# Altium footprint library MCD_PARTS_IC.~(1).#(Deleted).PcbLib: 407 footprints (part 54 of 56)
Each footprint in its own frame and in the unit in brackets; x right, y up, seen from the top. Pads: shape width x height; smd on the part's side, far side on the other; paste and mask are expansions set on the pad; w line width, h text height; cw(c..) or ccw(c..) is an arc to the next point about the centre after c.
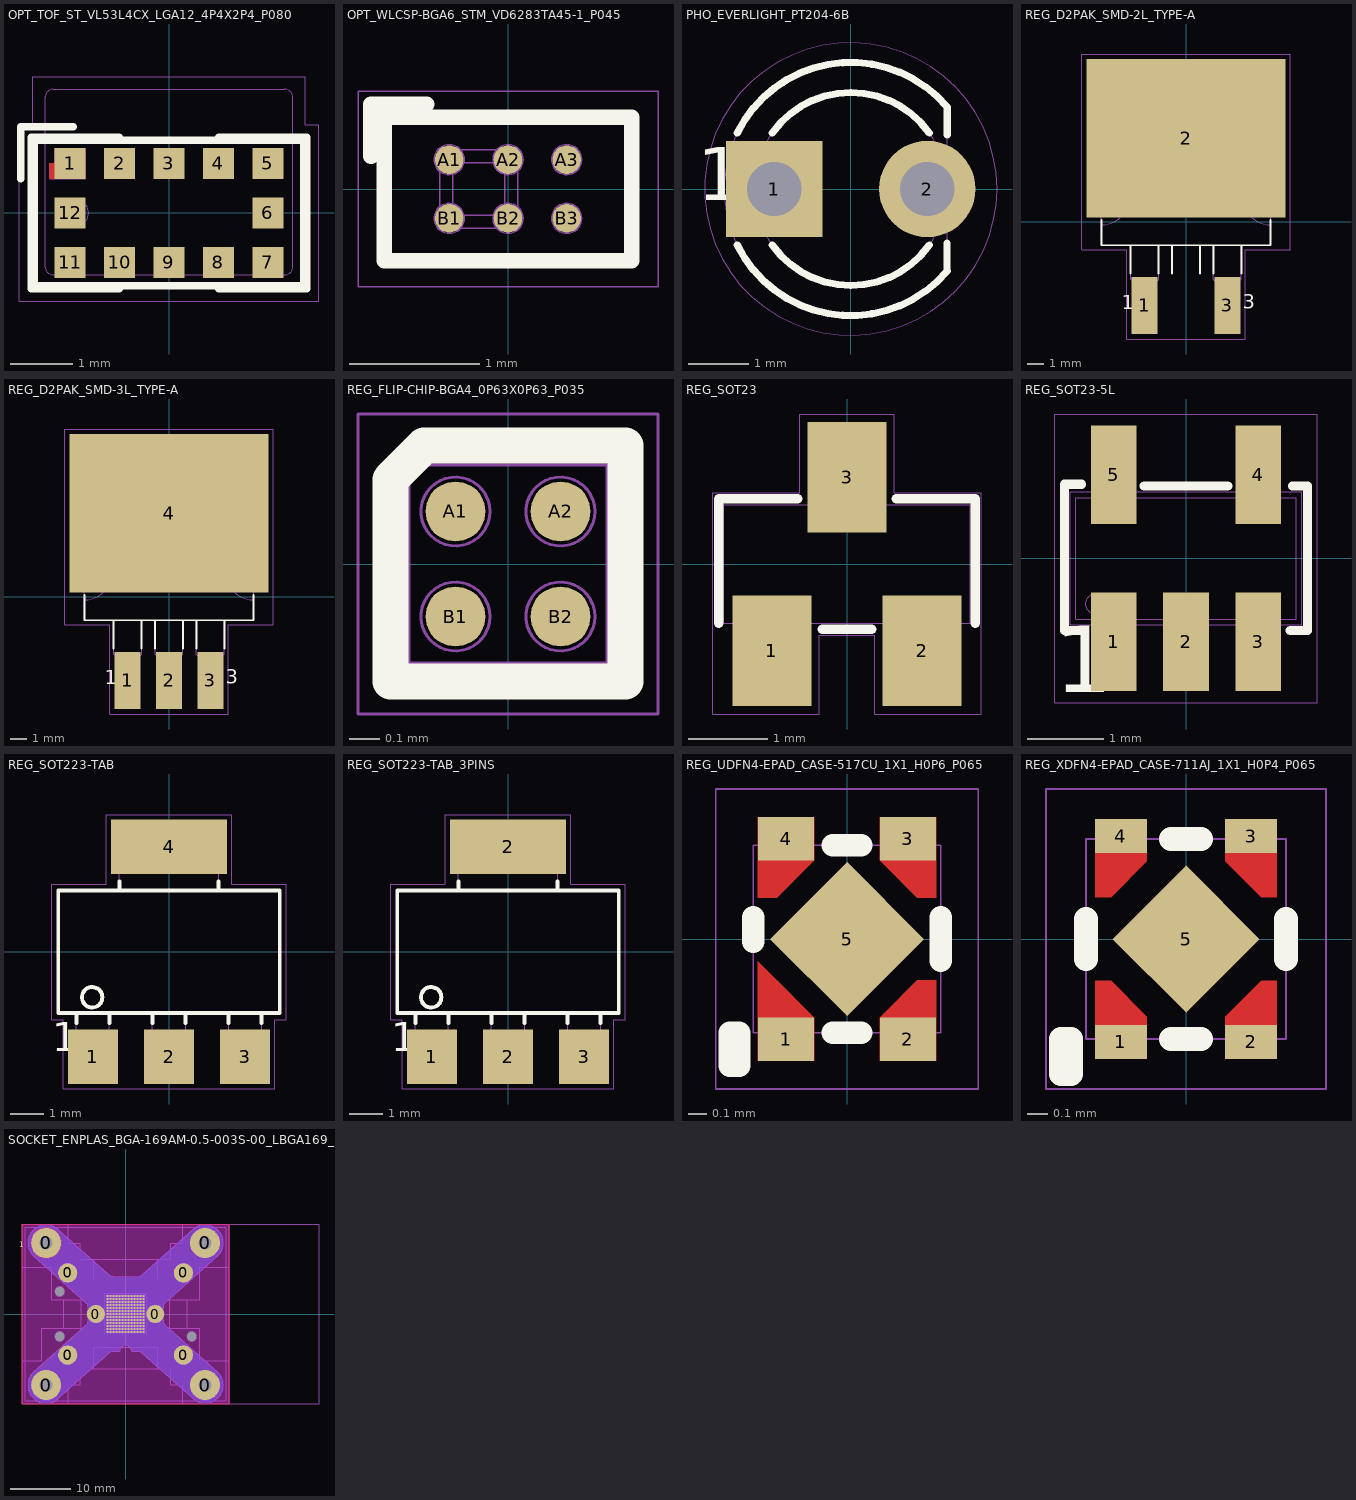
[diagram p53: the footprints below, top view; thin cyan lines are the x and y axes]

## OPT_TOF_ST_VL53L4CX_LGA12_4P4X2P4_P080 [mm]
height 1.1
pads (12):
  rect 0.5x0.5 smd mask+0.05: 1(-1.6,0.8) 2(-0.8,0.8) 3(0,0.8) 4(0.8,0.8) 5(1.6,0.8) 6(1.6,0) 7(1.6,-0.8) 8(0.8,-0.8) 9(0,-0.8) 10(-0.8,-0.8) 11(-1.6,-0.8) 12(-1.6,0)
Top Layer:
  region: -1.35,0.55 -1.93,0.55 -1.93,0.8 -1.85,0.8 -1.85,1.05 -1.35,1.05
Top Overlay:
  lines w0.12: -2.395,0.55 -2.395,1.395 -1.55,1.395 ; -0.8,-1.175 -0.8,-1.225 -2.225,-1.225 -2.225,1.225 -0.8,1.225 -0.8,1.175 ; 0.8,-1.175 0.8,-1.225 2.225,-1.225 2.225,1.225 0.8,1.225 0.8,1.175 ; -2.175,-1.175 2.175,-1.175 2.175,1.175 -2.175,1.175 -2.175,-1.175
M14-Top Assembly:
  circle w0.01: c1.5,0 r0.1
  circle w0.01: c-1.5,0 r0.2
  lines w0.01: -0.8,-1.175 -0.8,-1.225 -2.225,-1.225 -2.225,1.225 -0.8,1.225 -0.8,1.175 ; 0.8,-1.175 0.8,-1.225 2.225,-1.225 2.225,1.225 0.8,1.225 0.8,1.175 ; -2.175,-1.175 -2.175,1.175 2.175,1.175 2.175,-1.175 -2.175,-1.175 ; -2,-0.875 ccw(c-1.875,-0.875) -1.875,-1 1.875,-1 ccw(c1.875,-0.875) 2,-0.875 2,1.225 2,1.875 ccw(c1.875,1.875) 1.875,2 -1.875,2 ccw(c-1.875,1.875) -2,1.875 -2,-0.875 ; -1.93,0.55 -1.35,0.55 -1.35,1.05 -1.85,1.05 -1.85,0.8 -1.93,0.8 -1.93,0.55
  text "1" at -1.655,0.64 h0.5
  text "'.Designator'" at -2,-0.5 h0.75
  text "PROTECTIVE LINE" at -1.25,1.75 h0.3
  text "RESTRICTED ZONE H = 1mm" at -1.825,1.45 h0.3
M16-Top Courtyard:
  lines w0.01: -2.425,-1.425 -2.425,1.425 -2.2,1.425 -2.2,2.2 2.2,2.2 2.2,1.425 2.425,1.425 2.425,-1.425 -2.425,-1.425
  text "RESTRICTED ZONE H = 1mm" at -1.825,1.45 h0.3
  text "PROTECTIVE LINE" at -1.25,1.75 h0.3
3D body: height 1.08, standoff 1.04, extent -2,-1 2,2
3D body: height 1.1, standoff 0, extent -2.225,-1.225 2.225,1.225
3D body "vl53l0x.STEP": height 1.04, standoff 0, extent -2.2,-1.2 2.2,1.2

## OPT_WLCSP-BGA6_STM_VD6283TA45-1_P045 [mm] "MCD-02258"
height 0.615
pads (6):
  round 0.22 smd paste+0.025 mask+0.05: A1(-0.45,0.225) A2(0,0.225) A3(0.45,0.225) B1(-0.45,-0.225) B2(0,-0.225) B3(0.45,-0.225)
Top Overlay:
  lines w0.12: -1.05,0.25 -1.05,0.65 -0.625,0.65 ; -0.95,-0.55 -0.95,0.55 0.95,0.55 0.95,-0.55 -0.95,-0.55
M14-Top Assembly:
  circle w0.01: c-0.45,-0.225 r0.115
  circle w0.01: c0,-0.225 r0.115
  circle w0.01: c0.45,-0.225 r0.115
  circle w0.01: c0.45,0.225 r0.115
  circle w0.01: c0,0.225 r0.115
  circle w0.01: c-0.45,0.225 r0.115
  lines w0.01: -0.95,-0.55 0.95,-0.55 0.95,0.55 -0.95,0.55 -0.95,-0.55 ; -0.525,-0.3 -0.525,0.3 0.075,0.3 0.075,-0.3 -0.525,-0.3 ; -0.425,-0.2 -0.425,0.2 -0.025,0.2 -0.025,-0.2 -0.425,-0.2
  text "A1" at -0.9,0.15 h0.3
  text "'.Designator'" at -2,-0.375 h0.75
  text "B1" at -0.9,-0.325 h0.3
M16-Top Courtyard:
  lines w0.01: -1.15,-0.75 -1.15,0.75 1.15,0.75 1.15,-0.75 -1.15,-0.75
3D body: height 0.35, standoff 0.29, extent -0.313,-0.037 -0.238,0.038
3D body: height 0.35, standoff 0.29, extent -0.563,0.088 -0.488,0.163
3D body: height 0.35, standoff 0.29, extent -0.687,-0.287 -0.613,-0.212
3D body: height 0.35, standoff 0.29, extent -0.813,-0.162 -0.738,-0.088
3D body: height 0.35, standoff 0.29, extent -0.813,-0.037 -0.738,0.038
3D body: height 0.35, standoff 0.29, extent -0.687,-0.162 -0.613,-0.088
3D body: height 0.35, standoff 0.29, extent -0.563,-0.287 -0.488,-0.212
3D body: height 0.35, standoff 0.29, extent -0.313,0.088 -0.238,0.163
3D body: height 0.35, standoff 0.29, extent -0.437,0.213 -0.363,0.288
3D body: height 0.35, standoff 0.29, extent -0.437,0.088 -0.363,0.162
3D body: height 0.35, standoff 0.29, extent -0.563,0.213 -0.488,0.288
3D body: height 0.35, standoff 0.29, extent -0.313,-0.162 -0.238,-0.088
3D body: height 0.35, standoff 0.29, extent -0.437,-0.037 -0.363,0.038
3D body: height 0.35, standoff 0.29, extent -0.687,0.213 -0.613,0.288
3D body: height 0.35, standoff 0.29, extent -0.313,-0.287 -0.238,-0.212
3D body: height 0.35, standoff 0.29, extent -0.437,-0.162 -0.363,-0.088
3D body: height 0.35, standoff 0.29, extent -0.563,-0.037 -0.488,0.038
3D body: height 0.35, standoff 0.29, extent -0.687,0.088 -0.613,0.163
3D body: height 0.35, standoff 0.29, extent -0.813,0.213 -0.738,0.288
3D body: height 0.62, standoff 0.29, extent -0.95,-0.55 0.95,0.55
3D body: height 0.29, standoff 0.15, extent -0.95,-0.55 0.95,0.55
3D body: height 0.19, standoff -0.05, extent -0.558,-0.338 -0.335,-0.112
3D body: height 0.19, standoff -0.05, extent -0.108,-0.338 0.115,-0.112
3D body: height 0.19, standoff -0.05, extent 0.342,-0.338 0.565,-0.112
3D body: height 0.19, standoff -0.05, extent 0.342,0.112 0.565,0.338
3D body: height 0.19, standoff -0.05, extent -0.108,0.112 0.115,0.338
3D body: height 0.19, standoff -0.05, extent -0.558,0.112 -0.335,0.338

## PHO_EVERLIGHT_PT204-6B [mm] "MCD-01691"
height 7
pads (2):
  rect 1.6x1.6 hole 0.9 mask+0.05: 1(-1.27,0)
  round 1.6 hole 0.9 mask+0.05: 2(1.27,0)
Top Overlay:
  lines w0.12: -1.883,-0.929 ccw(c0,0) 1.599,-1.361 ; -1.883,0.929 cw(c0,0) 1.599,1.362 ; -1.304,-0.928 ccw(c0,0) 1.304,-0.928 ; -1.304,0.928 cw(c0,0) 1.304,0.928 ; 1.598,-1.361 1.598,-0.9 ; 1.6,0.9 1.6,1.362
  text "1" at -2.55,-0.475 h1.5
M14-Top Assembly:
  circle w0.01: c0,0 r1.6
  lines w0.01: 1.599,1.362 ccw(c0,0) 1.6,-1.36 1.6,1.362
  text "C" at 1.1,-0.25 h0.75
  text "E" at -1.525,-0.225 h0.75
  text "'.Designator'" at -2,0.25 h0.75
M16-Top Courtyard:
  circle w0.01: c0,0 r2.425
3D body: height 0.55, standoff -0.05, extent 0.97,-0.298 1.57,0.298
3D body: height 1.5, standoff 0.25, extent 0.973,-0.299 1.57,0.3
3D body: height 0, standoff -23.9, extent 1.02,-0.2 1.52,0.2
3D body: height 0.15, standoff 0, extent 1.02,-0.2 1.52,0.2
3D body: height 0.15, standoff 0, extent -1.52,-0.2 -1.02,0.2
3D body: height 0, standoff -24.9, extent -1.52,-0.2 -1.02,0.2
3D body: height 1.5, standoff 0.25, extent -1.567,-0.299 -0.97,0.3
3D body: height 0.55, standoff -0.05, extent -1.57,-0.298 -0.97,0.298
3D body: height 2.7, standoff 1.5, extent -2.1,-2.1 1.6,2.1
3D body: height 5.4, standoff 2.7, extent -1.6,-1.597 1.6,1.597
3D body: height 7, standoff 3.8, extent -1.588,-1.597 1.6,1.597

## REG_D2PAK_SMD-2L_TYPE-A [mm] "MCD-03390"
height 4.6
pads (3):
  rect 1.6x3.5 smd paste+0 mask+0.05: 1(-2.54,-5.138) 3(2.54,-5.138)
  rect 12.2x9.75 smd mask+0.05: 2(0,5.138)
Top Overlay:
  lines w0.12: -5.2,0.112 -5.2,-1.438 5.2,-1.438 5.2,0.112 ; -3.4,-3.188 -3.4,-1.438 ; -1.7,-3.188 -1.7,-1.438 ; -0.85,-3.188 -0.85,-1.438 ; 0.85,-3.188 0.85,-1.438 ; 1.7,-3.188 1.7,-1.438 ; 3.4,-3.188 3.4,-1.438
  text "1" at -3.95,-5.688 h1.5
  text "3" at 3.5,-5.638 h1.5
M14-Top Assembly:
  lines w0.01: -5.2,-0.188 ccw(c-5.2,1.512) -5.2,3.212 ; -5.2,6.912 5.2,6.912 ; -3.39,-1.438 -3.39,-3.538 -3.19,-3.738 ; -3.19,-1.438 -1.69,-1.438 -1.69,-3.538 -1.89,-3.738 ; 1.69,-1.438 1.69,-3.538 1.89,-3.738 ; 1.89,-1.438 3.39,-1.438 3.39,-3.538 3.19,-3.738 ; 5.2,-0.188 cw(c5.2,1.512) 5.2,3.212 ; -5.2,7.912 -5.2,-1.438 5.2,-1.438 5.2,7.912 ; -5.2,7.912 5.2,7.912 ; -5.2,7.912 -5.2,9.312 5.2,9.312 5.2,7.912 ; -3.19,-3.738 -1.89,-3.738 ; -3.19,-3.738 -1.89,-3.738 ; 1.89,-3.738 3.19,-3.738 ; 1.89,-3.738 3.19,-3.738 ; -3.04,-6.538 -3.04,-3.738 -2.04,-3.738 -2.04,-6.538 -3.04,-6.538 ; 2.04,-6.538 2.04,-3.738 3.04,-3.738 3.04,-6.538 2.04,-6.538
  text "2" at -0.35,3.312 h1.5
  text "1" at -2.743,-6.272 h1.5
  text "3" at 2.257,-6.297 h1.5
  text "'.Designator'" at 0,0 h0.75
M16-Top Courtyard:
  lines w0.01: -6.4,-1.7 -6.4,0.85 -6.4,4.4 -6.4,10.3 6.4,10.3 6.4,-1.7 5.45,-1.7 3.65,-1.7 3.65,-7.2 -3.65,-7.2 -3.65,-3.75 -3.65,-1.7 -5.45,-1.7 -6.4,-1.7
3D body: height 2.7, standoff 2.4, extent -0.85,-4.038 0.85,-1.438
3D body: height 2.7, standoff 0.3, extent 2.04,-4.038 3.04,-3.738
3D body: height 2.7, standoff 0.3, extent -3.04,-4.038 -2.04,-3.738
3D body: height 0.3, standoff 0, extent 2.04,-6.538 3.04,-3.738
3D body: height 2.7, standoff 2.4, extent 1.69,-4.038 3.39,-1.438
3D body: height 0.3, standoff 0, extent -3.04,-6.538 -2.04,-3.738
3D body: height 2.7, standoff 2.4, extent -3.39,-4.038 -1.69,-1.438
3D body: height 4.6, standoff 1.4, extent -5.2,-1.438 5.2,7.912
3D body: height 1.4, standoff 0, extent -5.2,-1.438 5.2,7.912
3D body: height 1.4, standoff 0, extent -5.2,7.912 5.2,9.312

## REG_D2PAK_SMD-3L_TYPE-A [mm] "MCD-02365"
height 4.6
pads (4):
  rect 1.6x3.5 smd paste+0 mask+0.05: 1(-2.54,-5.138) 2(0,-5.138) 3(2.54,-5.138)
  rect 12.2x9.75 smd mask+0.05: 4(0,5.138)
Top Overlay:
  lines w0.12: -5.2,0.112 -5.2,-1.438 5.2,-1.438 5.2,0.112 ; -3.4,-3.188 -3.4,-1.438 ; -1.7,-3.188 -1.7,-1.438 ; -0.85,-3.188 -0.85,-1.438 ; 0.85,-3.188 0.85,-1.438 ; 1.7,-3.188 1.7,-1.438 ; 3.4,-3.188 3.4,-1.438
  text "1" at -3.95,-5.688 h1.5
  text "3" at 3.5,-5.638 h1.5
M14-Top Assembly:
  lines w0.01: -5.2,-0.188 ccw(c-5.2,1.512) -5.2,3.212 ; -5.2,6.912 5.2,6.912 ; -3.39,-1.438 -3.39,-3.538 -3.19,-3.738 ; -3.19,-1.438 -1.69,-1.438 -1.69,-3.538 -1.89,-3.738 ; -0.85,-1.438 -0.85,-3.538 -0.65,-3.738 ; -0.65,-1.438 0.85,-1.438 0.85,-3.538 0.65,-3.738 ; 1.69,-1.438 1.69,-3.538 1.89,-3.738 ; 1.89,-1.438 3.39,-1.438 3.39,-3.538 3.19,-3.738 ; 5.2,-0.188 cw(c5.2,1.512) 5.2,3.212 ; -5.2,7.912 -5.2,-1.438 5.2,-1.438 5.2,7.912 ; -5.2,7.912 5.2,7.912 ; -5.2,7.912 -5.2,9.312 5.2,9.312 5.2,7.912 ; -3.19,-3.738 -1.89,-3.738 ; -3.19,-3.738 -1.89,-3.738 ; -0.65,-3.738 0.65,-3.738 ; -0.65,-3.738 -0.65,-6.538 0.65,-6.538 0.65,-3.738 ; -0.65,-3.738 0.65,-3.738 ; 1.89,-3.738 3.19,-3.738 ; 1.89,-3.738 3.19,-3.738 ; -3.04,-6.538 -3.04,-3.738 -2.04,-3.738 -2.04,-6.538 -3.04,-6.538 ; 2.04,-6.538 2.04,-3.738 3.04,-3.738 3.04,-6.538 2.04,-6.538
  text "4" at -0.35,3.312 h1.5
  text "1" at -2.743,-6.272 h1.5
  text "3" at 2.257,-6.297 h1.5
  text "2" at -0.293,-6.297 h1.5
  text "'.Designator'" at -2,-0.5 h0.75
M16-Top Courtyard:
  lines w0.01: -6.4,-1.7 -6.4,0.85 -6.4,4.4 -6.4,10.3 6.4,10.3 6.4,-1.7 5.45,-1.7 3.65,-1.7 3.65,-7.2 -3.65,-7.2 -3.65,-3.75 -3.65,-1.7 -5.45,-1.7 -6.4,-1.7
3D body: height 2.7, standoff 0.3, extent 2.04,-4.038 3.04,-3.738
3D body: height 2.7, standoff 0.3, extent -0.65,-4.038 0.65,-3.738
3D body: height 2.7, standoff 0.3, extent -3.04,-4.038 -2.04,-3.738
3D body: height 0.3, standoff 0, extent 2.04,-6.538 3.04,-3.738
3D body: height 2.7, standoff 2.4, extent 1.69,-4.038 3.39,-1.438
3D body: height 2.7, standoff 2.4, extent -0.85,-4.038 0.85,-1.438
3D body: height 0.3, standoff 0, extent -0.65,-6.538 0.65,-3.738
3D body: height 0.3, standoff 0, extent -3.04,-6.538 -2.04,-3.738
3D body: height 2.7, standoff 2.4, extent -3.39,-4.038 -1.69,-1.438
3D body: height 4.6, standoff 1.4, extent -5.2,-1.438 5.2,7.912
3D body: height 1.4, standoff 0, extent -5.2,-1.438 5.2,7.912
3D body: height 1.4, standoff 0, extent -5.2,7.912 5.2,9.312

## REG_FLIP-CHIP-BGA4_0P63X0P63_P035 [mm] "MCD-03556"
height 0.45
pads (4):
  round 0.2 smd paste+0.019 mask+0.038: A1(-0.175,0.175) A2(0.175,0.175) B1(-0.175,-0.175) B2(0.175,-0.175)
Top Overlay:
  lines w0.12: 0.392,0.394 -0.28,0.394 -0.392,0.282 -0.392,0.28 -0.392,-0.392 0.392,-0.392 0.392,0.392
M14-Top Assembly:
  circle w0.01: c-0.175,0.175 r0.115
  circle w0.01: c-0.175,-0.175 r0.115
  circle w0.01: c0.175,0.175 r0.115
  circle w0.01: c0.175,-0.175 r0.115
  lines w0.01: -0.33,-0.33 -0.33,0.33 0.33,0.33 0.33,-0.33 -0.33,-0.33
  text "'.Designator'" at -2,-0.5 h0.75
  text "A1" at -0.314,0.079 h0.3
M16-Top Courtyard:
  lines w0.01: -0.5,-0.5 0.5,-0.5 0.5,0.5 -0.5,0.5 -0.5,-0.5
3D body: height 0.23, standoff -0.01, extent 0.055,0.055 0.295,0.295
3D body: height 0.45, standoff 0.21, extent -0.33,-0.33 0.33,0.33
3D body: height 0.46, standoff 0.45, extent -0.275,0.075 -0.075,0.275
3D body: height 0.23, standoff -0.01, extent -0.295,0.055 -0.055,0.295
3D body: height 0.23, standoff -0.01, extent -0.295,-0.295 -0.055,-0.055
3D body: height 0.23, standoff -0.01, extent 0.055,-0.295 0.295,-0.055

## REG_SOT23 [mm]
height 1.1
pads (3):
  rect 1x1.4 smd mask+0.05: 1(-0.95,-1.1) 2(0.95,-1.1) 3(0,1.1)
Top Overlay:
  lines w0.12: -1.625,-0.75 -1.625,0.825 -0.624,0.825 ; -0.312,-0.825 0.312,-0.825 ; 0.624,0.825 1.625,0.825 1.625,-0.75
M14-Top Assembly:
  lines w0.01: -1.56,-0.75 1.56,-0.75 1.56,0.75 -1.56,0.75 -1.56,-0.75 ; -1.275,-1.025 -1.275,-0.75 -0.675,-0.75 -0.675,-1.025 -1.275,-1.025 ; -0.25,0.75 -0.25,1.05 0.325,1.05 0.325,0.75 -0.25,0.75 ; 0.65,-1.025 0.65,-0.75 1.25,-0.75 1.25,-1.025 0.65,-1.025
  text "'.Designator'" at -2,-0.5 h0.75
M16-Top Courtyard:
  lines w0.01: -1.7,-1.9 -1.7,0.9 -0.6,0.9 -0.6,1.9 0.6,1.9 0.6,0.9 1.7,0.9 1.7,-1.9 0.35,-1.9 0.35,-0.9 -0.35,-0.9 -0.35,-1.9 -1.7,-1.9
3D body "SOT23-3_TO-236AB.STEP": height 1.09, standoff 0, extent -1.5,-1.25 1.5,1.25
3D body: height 1.1, standoff 0, extent -1.559,-0.749 1.559,0.749

## REG_SOT23-5L [mm]
height 0.9
pads (5):
  rect 0.6x1.3 smd mask+0.05: 1(-0.95,-1.1) 2(0,-1.1) 3(0.95,-1.1) 4(0.95,1.1) 5(-0.95,1.1)
Top Overlay:
  lines w0.12: -1.375,0.975 -1.6,0.975 -1.6,-0.95 -1.372,-0.95 ; -0.55,0.95 0.55,0.95 ; 1.372,-0.95 1.6,-0.95 1.6,0.95 1.4,0.95
  text "1" at -1.725,-2.05 h1.5
M14-Top Assembly:
  circle w0.01: c-1.2,-0.6 r0.125
  lines w0.01: -1.15,-0.875 -1.15,-1.5 -0.75,-1.5 -0.75,-0.875 ; -1.15,0.875 -1.15,1.5 -0.75,1.5 -0.75,0.875 ; -0.2,-0.875 -0.2,-1.5 0.2,-1.5 0.2,-0.875 ; 0.75,-0.875 0.75,-1.5 1.15,-1.5 1.15,-0.875 ; 0.75,0.875 0.75,1.5 1.15,1.5 1.15,0.875 ; -1.525,-0.875 -1.525,0.875 1.525,0.875 1.525,-0.875 -1.525,-0.875 ; -1.45,-0.8 1.45,-0.8 1.45,0.8 -1.45,0.8 -1.45,-0.8
  text "'.Designator'" at -2,-0.5 h0.75
M16-Top Courtyard:
  lines w0.01: -1.725,-1.9 -1.725,1.9 1.725,1.9 1.725,-1.9 -1.725,-1.9
3D body "SOT23-5L.STEP": height 1.1, standoff 0, extent -1.5,-1.25 1.5,1.25
3D body: height 0.9, standoff 0, extent -1.524,-0.874 1.524,0.874

## REG_SOT223-TAB [mm]
height 1.8
pads (4):
  rect 1.5x1.65 smd mask+0.05: 1(-2.3,-3.175) 2(0,-3.175) 3(2.3,-3.175)
  rect 3.5x1.65 smd mask+0.05: 4(0,3.175)
Top Overlay:
  circle w0.12: c-2.325,-1.375 r0.309
  lines w0.12: -2.8,-2.15 -2.8,-1.85 -1.8,-1.85 -1.8,-2.15 ; -1.5,2.125 -1.5,1.85 1.5,1.85 1.5,2.125 ; -0.5,-2.15 -0.5,-1.85 0.5,-1.85 0.5,-2.15 ; 1.8,-2.15 1.8,-1.85 2.8,-1.85 2.8,-2.15 ; -3.35,-1.85 -3.35,1.85 3.35,1.85 3.35,-1.85 -3.35,-1.85
  text "1" at -3.525,-3.3 h1.5
M14-Top Assembly:
  circle w0.01: c-2.325,-1.375 r0.285
  lines w0.01: -3.35,-1.85 -3.35,1.85 3.35,1.85 3.35,-1.85 -3.35,-1.85 ; -2.8,-3.65 -1.8,-3.65 -1.8,-1.85 -2.8,-1.85 -2.8,-3.65 ; -1.5,1.85 1.5,1.85 1.5,3.65 -1.5,3.65 -1.5,1.85 ; -0.5,-3.65 0.5,-3.65 0.5,-1.85 -0.5,-1.85 -0.5,-3.65 ; 1.8,-3.65 2.8,-3.65 2.8,-1.85 1.8,-1.85 1.8,-3.65
  text "'.Designator'" at -2,-0.5 h0.75
  text "3" at 1.95,-3.4 h1.5
  text "2" at -0.35,-3.375 h1.5
  text "1" at -2.5,-3.35 h1.5
  text "4" at -0.325,2.375 h1.5
M16-Top Courtyard:
  lines w0.01: -3.55,-2.05 -3.55,2.05 -1.9,2.05 -1.9,4.15 1.9,4.15 1.9,2.05 3.55,2.05 3.55,-2.05 3.2,-2.05 3.2,-4.15 -3.2,-4.15 -3.2,-2.05 -3.55,-2.05
3D body "SOT223.STEP": height 1.68, standoff 0, extent -3.25,-3.48 3.25,3.48
3D body: height 1.8, standoff 0, extent -3.349,-1.849 3.349,1.849

## REG_SOT223-TAB_3PINS [mm] "MCD-04293"
height 1.8
pads (4):
  rect 1.5x1.65 smd mask+0.05: 1(-2.3,-3.175) 2(0,-3.175) 3(2.3,-3.175)
  rect 3.5x1.65 smd mask+0.05: 2(0,3.175)
Top Overlay:
  circle w0.12: c-2.325,-1.375 r0.309
  lines w0.12: -2.8,-2.15 -2.8,-1.85 -1.8,-1.85 -1.8,-2.15 ; -1.5,2.125 -1.5,1.85 1.5,1.85 1.5,2.125 ; -0.5,-2.15 -0.5,-1.85 0.5,-1.85 0.5,-2.15 ; 1.8,-2.15 1.8,-1.85 2.8,-1.85 2.8,-2.15 ; -3.35,-1.85 -3.35,1.85 3.35,1.85 3.35,-1.85 -3.35,-1.85
  text "1" at -3.525,-3.3 h1.5
M14-Top Assembly:
  circle w0.01: c-2.325,-1.375 r0.285
  lines w0.01: -3.35,-1.85 -3.35,1.85 3.35,1.85 3.35,-1.85 -3.35,-1.85 ; -2.8,-3.65 -1.8,-3.65 -1.8,-1.85 -2.8,-1.85 -2.8,-3.65 ; -1.5,1.85 1.5,1.85 1.5,3.65 -1.5,3.65 -1.5,1.85 ; -0.5,-3.65 0.5,-3.65 0.5,-1.85 -0.5,-1.85 -0.5,-3.65 ; 1.8,-3.65 2.8,-3.65 2.8,-1.85 1.8,-1.85 1.8,-3.65
  text "'.Designator'" at 0,0 h0.75
  text "3" at 1.95,-3.4 h1.5
  text "2" at -0.35,-3.375 h1.5
  text "1" at -2.5,-3.35 h1.5
  text "2" at -0.325,2.375 h1.5
M16-Top Courtyard:
  lines w0.01: -3.55,-2.05 -3.55,2.05 -1.9,2.05 -1.9,4.15 1.9,4.15 1.9,2.05 3.55,2.05 3.55,-2.05 3.2,-2.05 3.2,-4.15 -3.2,-4.15 -3.2,-2.05 -3.55,-2.05
3D body "SOT223.STEP": height 1.68, standoff 0, extent -3.25,-3.48 3.25,3.48
3D body: height 1.8, standoff 0, extent -3.349,-1.849 3.349,1.849

## REG_UDFN4-EPAD_CASE-517CU_1X1_H0P6_P065 [mm] "MCD-01614"
height 0.6
pads (5):
  rect 0.3x0.23 smd paste-10 mask-10: 1(-0.325,-0.535) 2(0.325,-0.535) 3(0.325,0.535) 4(-0.325,0.535)
  rect 0.58x0.58 smd rot 45 paste+0 mask+0.017: 5(0,0)
Top Layer:
  region: -0.475,0.65 -0.175,0.65 -0.175,0.42 -0.375,0.22 -0.475,0.22
  region: 0.475,0.65 0.175,0.65 0.175,0.42 0.375,0.22 0.475,0.22
  region: -0.475,-0.65 -0.175,-0.65 -0.175,-0.42 -0.475,-0.12
  region: 0.475,-0.65 0.175,-0.65 0.175,-0.42 0.375,-0.22 0.475,-0.22
  lines w0.001: 0.035,-0.33 0.035,-0.33
Top Overlay:
  lines w0.12: -0.5,-0.015 -0.5,0.115 ; -0.075,-0.5 0.075,-0.5 ; -0.075,0.5 0.075,0.5 ; 0.5,-0.115 0.5,0.115 ; -0.625,-0.675 -0.625,-0.5 -0.575,-0.5 -0.575,-0.675 -0.625,-0.675
M14-Top Assembly:
  lines w0.01: -0.45,-0.5 -0.45,-0.225 -0.375,-0.225 -0.2,-0.4 -0.2,-0.5 ; -0.45,0.5 -0.45,0.225 -0.375,0.225 -0.2,0.4 -0.2,0.5 ; 0.2,-0.5 0.2,-0.4 0.375,-0.225 0.45,-0.225 0.45,-0.5 ; 0.2,0.5 0.2,0.4 0.375,0.225 0.45,0.225 0.45,0.5 ; -0.5,-0.5 0.5,-0.5 0.5,0.5 -0.5,0.5 -0.5,-0.5 ; -0.325,0 0,-0.325 0.325,0 0,0.325 -0.325,0
  text "5" at -0.05,-0.075 h0.25
  text "4" at -0.4,0.325 h0.25
  text "3" at 0.3,0.325 h0.25
  text "2" at 0.3,-0.475 h0.25
  text "1" at -0.4,-0.475 h0.25
  text "'.Designator'" at -2,-0.5 h0.75
M16-Top Courtyard:
  lines w0.01: -0.7,-0.8 -0.7,0.8 0.7,0.8 0.7,-0.8 -0.7,-0.8
3D body: height 0.6, standoff 0, extent -0.5,-0.5 0.5,0.5
3D body: height 0.61, standoff 0.6, extent -0.444,-0.445 -0.205,-0.205

## REG_XDFN4-EPAD_CASE-711AJ_1X1_H0P4_P065 [mm] "MCD-01613"
height 0.43
pads (5):
  rect 0.26x0.17 smd paste-10 mask-10: 1(-0.325,-0.515) 2(0.325,-0.515) 3(0.325,0.515) 4(-0.325,0.515)
  rect 0.52x0.52 smd rot 45 paste+0 mask+0.038: 5(0,0)
Top Layer:
  region: -0.455,0.6 -0.195,0.6 -0.195,0.39 -0.375,0.21 -0.455,0.21
  region: 0.455,0.6 0.195,0.6 0.195,0.39 0.375,0.21 0.455,0.21
  region: -0.455,-0.6 -0.195,-0.6 -0.195,-0.39 -0.375,-0.21 -0.455,-0.21
  region: 0.455,-0.6 0.195,-0.6 0.195,-0.39 0.375,-0.21 0.455,-0.21
Top Overlay:
  lines w0.12: -0.5,-0.1 -0.5,0.1 ; -0.075,-0.5 0.075,-0.5 ; -0.075,0.5 0.075,0.5 ; 0.5,-0.1 0.5,0.1 ; -0.625,-0.675 -0.575,-0.675 -0.575,-0.5 -0.625,-0.5 -0.625,-0.675
M14-Top Assembly:
  lines w0.01: -0.45,-0.5 -0.45,-0.225 -0.375,-0.225 -0.2,-0.4 -0.2,-0.5 ; -0.45,0.5 -0.45,0.225 -0.375,0.225 -0.2,0.4 -0.2,0.5 ; 0.2,-0.5 0.2,-0.4 0.375,-0.225 0.45,-0.225 0.45,-0.5 ; 0.2,0.5 0.2,0.4 0.375,0.225 0.45,0.225 0.45,0.5 ; -0.5,-0.5 -0.5,0.5 0.5,0.5 0.5,-0.5 -0.5,-0.5 ; -0.325,0 0,0.325 0.325,0 0,-0.325 -0.325,0
  text "'.Designator'" at -2,-0.5 h0.75
  text "1" at -0.4,-0.475 h0.25
  text "2" at 0.3,-0.475 h0.25
  text "3" at 0.3,0.325 h0.25
  text "4" at -0.4,0.325 h0.25
  text "5" at -0.05,-0.075 h0.25
M16-Top Courtyard:
  lines w0.01: -0.7,-0.75 0.7,-0.75 0.7,0.75 -0.7,0.75 -0.7,-0.75
3D body "XDFN4-711AJ.STEP": height 0.36, standoff -0.03, extent -0.5,-0.502 0.5,0.502
3D body: height 0.44, standoff 0.43, extent -0.444,-0.445 -0.205,-0.205
3D body: height 0.37, standoff 0.36, extent -0.469,-0.47 -0.23,-0.23
3D body: height 0.43, standoff 0, extent -0.5,-0.5 0.5,0.5

## SOCKET_ENPLAS_BGA-169AM-0.5-003S-00_LBGA169_P050_3D-CLOSE [mm] "MCD-02114"
height 41
pads (182):
  round 5 hole 2.15 mask+0.05: 0(-13.25,-11.85) 0(-13.25,11.85) 0(13.25,-11.85) 0(13.25,11.85)
  round 0 hole 1.6 unplated mask+0.05: 0(-11,-3.75) 0(-11,3.75) 0(11,-3.75)
  round 3.2 smd paste-2 mask+0.05: 0(-9.65,-6.85) 0(-9.65,6.85) 0(9.65,-6.85) 0(9.65,6.85)
  round 3 smd paste-2 mask+0.05: 0(-4.945,0) 0(4.945,0)
  rrect30% 0.35x0.35 smd paste-0.2 mask+0.05: A1(-3,3) A2(-2.5,3) A3(-2,3) A4(-1.5,3) A5(-1,3) A6(-0.5,3) A7(0,3) A8(0.5,3) A9(1,3) A10(1.5,3) A11(2,3) A12(2.5,3) A13(3,3) B1(-3,2.5) B2(-2.5,2.5) B3(-2,2.5) B4(-1.5,2.5) B5(-1,2.5) B6(-0.5,2.5) B7(0,2.5) B8(0.5,2.5) B9(1,2.5) B10(1.5,2.5) B11(2,2.5) B12(2.5,2.5) B13(3,2.5) C1(-3,2) C2(-2.5,2) C3(-2,2) C4(-1.5,2) C5(-1,2) C6(-0.5,2) C7(0,2) C8(0.5,2) C9(1,2) C10(1.5,2) C11(2,2) C12(2.5,2) C13(3,2) D1(-3,1.5) D2(-2.5,1.5) D3(-2,1.5) D4(-1.5,1.5) D5(-1,1.5) D6(-0.5,1.5) D7(0,1.5) D8(0.5,1.5) D9(1,1.5) D10(1.5,1.5) D11(2,1.5) D12(2.5,1.5) D13(3,1.5) E1(-3,1) E2(-2.5,1) E3(-2,1) E4(-1.5,1) E5(-1,1) E6(-0.5,1) E7(0,1) E8(0.5,1) E9(1,1) E10(1.5,1) E11(2,1) E12(2.5,1) E13(3,1) F1(-3,0.5) F2(-2.5,0.5) F3(-2,0.5) F4(-1.5,0.5) F5(-1,0.5) F6(-0.5,0.5) F7(0,0.5) F8(0.5,0.5) F9(1,0.5) F10(1.5,0.5) F11(2,0.5) F12(2.5,0.5) F13(3,0.5) G1(-3,0) G2(-2.5,0) G3(-2,0) G4(-1.5,0) G5(-1,0) G6(-0.5,0) G7(0,0) G8(0.5,0) G9(1,0) G10(1.5,0) G11(2,0) G12(2.5,0) G13(3,0) H1(-3,-0.5) H2(-2.5,-0.5) H3(-2,-0.5) H4(-1.5,-0.5) H5(-1,-0.5) H6(-0.5,-0.5) H7(0,-0.5) H8(0.5,-0.5) H9(1,-0.5) H10(1.5,-0.5) H11(2,-0.5) H12(2.5,-0.5) H13(3,-0.5) J1(-3,-1) J2(-2.5,-1) J3(-2,-1) J4(-1.5,-1) J5(-1,-1) J6(-0.5,-1) J7(0,-1) J8(0.5,-1) J9(1,-1) J10(1.5,-1) J11(2,-1) J12(2.5,-1) J13(3,-1) K1(-3,-1.5) K2(-2.5,-1.5) K3(-2,-1.5) K4(-1.5,-1.5) K5(-1,-1.5) K6(-0.5,-1.5) K7(0,-1.5) K8(0.5,-1.5) K9(1,-1.5) K10(1.5,-1.5) K11(2,-1.5) K12(2.5,-1.5) K13(3,-1.5) L1(-3,-2) L2(-2.5,-2) L3(-2,-2) L4(-1.5,-2) L5(-1,-2) L6(-0.5,-2) L7(0,-2) L8(0.5,-2) L9(1,-2) L10(1.5,-2) L11(2,-2) L12(2.5,-2) L13(3,-2) M1(-3,-2.5) M2(-2.5,-2.5) M3(-2,-2.5) M4(-1.5,-2.5) M5(-1,-2.5) M6(-0.5,-2.5) M7(0,-2.5) M8(0.5,-2.5) M9(1,-2.5) M10(1.5,-2.5) M11(2,-2.5) M12(2.5,-2.5) M13(3,-2.5) N1(-3,-3) N2(-2.5,-3) N3(-2,-3) N4(-1.5,-3) N5(-1,-3) N6(-0.5,-3) N7(0,-3) N8(0.5,-3) N9(1,-3) N10(1.5,-3) N11(2,-3) N12(2.5,-3) N13(3,-3)
Top Layer:
  circle w0.01: c-13.25,11.85 r2.5
  circle w0.01: c-13.25,11.85 r1.075
  lines w0.1: -17.25,-15 17.275,-15 17.275,15 -17.25,15 -17.25,-15
Top Layer keep-out:
  region: 4.975,15 4.975,1.5 4.95,1.5 4.803,1.493 4.515,1.435 4.243,1.323 3.998,1.16 3.79,0.952 3.627,0.707 3.515,0.435 3.457,0.147 3.45,0 3.457,-0.147 3.515,-0.435 3.627,-0.707 3.79,-0.952 3.998,-1.16 4.243,-1.323 4.515,-1.435 4.803,-1.493 4.95,-1.5 4.975,-1.5 4.975,-15 0,-15 0,-3.375 3.375,-3.375 3.375,3.375 -3.375,3.375 -3.375,-3.375 0,-3.375 0,-15 -4.95,-15 -4.95,-1.5 -4.803,-1.493 -4.515,-1.435 -4.243,-1.323 -3.998,-1.16 -3.79,-0.952 -3.627,-0.707 -3.515,-0.435 -3.457,-0.147 -3.45,0 -3.457,0.147 -3.515,0.435 -3.627,0.707 -3.79,0.952 -3.998,1.16 -4.243,1.323 -4.515,1.435 -4.803,1.493 -4.95,1.5 -4.95,15
  region: 9.675,15 4.975,15 4.975,1.5 5.122,1.493 5.41,1.435 5.682,1.323 5.927,1.16 6.135,0.952 6.298,0.707 6.41,0.435 6.468,0.147 6.475,0 6.468,-0.147 6.41,-0.435 6.298,-0.707 6.135,-0.952 5.927,-1.16 5.682,-1.323 5.41,-1.435 5.122,-1.493 4.975,-1.5 4.975,-15 9.675,-15 9.675,-8.45 9.518,-8.442 9.211,-8.381 8.921,-8.261 8.66,-8.087 8.438,-7.865 8.264,-7.604 8.144,-7.314 8.083,-7.007 8.075,-6.85 8.083,-6.693 8.144,-6.386 8.264,-6.096 8.438,-5.835 8.66,-5.613 8.921,-5.439 9.211,-5.319 9.518,-5.258 9.675,-5.25 9.675,-4.9 11.025,-4.9 11.025,-4.55 10.947,-4.546 10.793,-4.516 10.648,-4.456 10.517,-4.368 10.407,-4.258 10.319,-4.127 10.259,-3.982 10.229,-3.828 10.225,-3.75 10.229,-3.672 10.259,-3.518 10.319,-3.373 10.407,-3.242 10.517,-3.132 10.648,-3.044 10.793,-2.984 10.947,-2.954 11.025,-2.95 11.025,4.925 9.675,4.925 9.675,5.25 9.518,5.258 9.211,5.319 8.921,5.439 8.66,5.613 8.438,5.835 8.264,6.096 8.144,6.386 8.083,6.693 8.075,6.85 8.083,7.007 8.144,7.314 8.264,7.604 8.438,7.865 8.66,8.087 8.921,8.261 9.211,8.381 9.518,8.442 9.675,8.45
  region: -9.65,15 -4.95,15 -4.95,1.5 -5.097,1.493 -5.385,1.435 -5.657,1.323 -5.902,1.16 -6.11,0.952 -6.273,0.707 -6.385,0.435 -6.443,0.147 -6.45,0 -6.443,-0.147 -6.385,-0.435 -6.273,-0.707 -6.11,-0.952 -5.902,-1.16 -5.657,-1.323 -5.385,-1.435 -5.097,-1.493 -4.95,-1.5 -4.95,-15 -9.65,-15 -9.65,-8.45 -9.493,-8.442 -9.186,-8.381 -8.896,-8.261 -8.635,-8.087 -8.413,-7.865 -8.239,-7.604 -8.119,-7.314 -8.058,-7.007 -8.05,-6.85 -8.058,-6.693 -8.119,-6.386 -8.239,-6.096 -8.413,-5.835 -8.635,-5.613 -8.896,-5.439 -9.186,-5.319 -9.493,-5.258 -9.65,-5.25 -9.65,-4.9 -11,-4.9 -11,-4.55 -10.922,-4.546 -10.768,-4.516 -10.623,-4.456 -10.492,-4.368 -10.382,-4.258 -10.294,-4.127 -10.234,-3.982 -10.204,-3.828 -10.2,-3.75 -10.204,-3.672 -10.234,-3.518 -10.294,-3.373 -10.382,-3.242 -10.492,-3.132 -10.623,-3.044 -10.768,-2.984 -10.922,-2.954 -11,-2.95 -11,2.95 -10.922,2.954 -10.768,2.984 -10.623,3.044 -10.492,3.132 -10.382,3.242 -10.294,3.373 -10.234,3.518 -10.204,3.672 -10.2,3.75 -10.204,3.828 -10.234,3.982 -10.294,4.127 -10.382,4.258 -10.492,4.368 -10.623,4.456 -10.768,4.516 -10.922,4.546 -11,4.55 -11,4.925 -9.65,4.925 -9.65,5.25 -9.493,5.258 -9.186,5.319 -8.896,5.439 -8.635,5.613 -8.413,5.835 -8.239,6.096 -8.119,6.386 -8.058,6.693 -8.05,6.85 -8.058,7.007 -8.119,7.314 -8.239,7.604 -8.413,7.865 -8.635,8.087 -8.896,8.261 -9.186,8.381 -9.493,8.442 -9.65,8.45
  region: -17.25,15 -13.25,15 -13.25,14.347 -13.253,14.347 -13.498,14.335 -13.978,14.239 -14.43,14.052 -14.837,13.78 -15.183,13.434 -15.455,13.027 -15.642,12.575 -15.738,12.095 -15.75,11.85 -15.738,11.605 -15.642,11.125 -15.455,10.673 -15.183,10.266 -14.837,9.92 -14.43,9.648 -13.978,9.461 -13.498,9.365 -13.253,9.353 -13.25,9.353 -13.25,-9.353 -13.253,-9.353 -13.498,-9.365 -13.978,-9.461 -14.43,-9.648 -14.837,-9.92 -15.183,-10.266 -15.455,-10.673 -15.642,-11.125 -15.738,-11.605 -15.75,-11.85 -15.738,-12.095 -15.642,-12.575 -15.455,-13.027 -15.183,-13.434 -14.837,-13.78 -14.43,-14.052 -13.978,-14.239 -13.498,-14.335 -13.253,-14.347 -13.25,-14.347 -13.25,-15 -17.25,-15
  region: 17.275,15 13.275,15 13.275,14.347 13.278,14.347 13.523,14.335 14.003,14.239 14.455,14.052 14.862,13.78 15.208,13.434 15.48,13.027 15.667,12.575 15.763,12.095 15.775,11.85 15.763,11.605 15.667,11.125 15.48,10.673 15.208,10.266 14.862,9.92 14.455,9.648 14.003,9.461 13.523,9.365 13.278,9.353 13.275,9.353 13.275,-9.353 13.278,-9.353 13.523,-9.365 14.003,-9.461 14.455,-9.648 14.862,-9.92 15.208,-10.266 15.48,-10.673 15.667,-11.125 15.763,-11.605 15.775,-11.85 15.763,-12.095 15.667,-12.575 15.48,-13.027 15.208,-13.434 14.862,-13.78 14.455,-14.052 14.003,-14.239 13.523,-14.335 13.278,-14.347 13.275,-14.347 13.275,-15 17.275,-15
  region: -13.25,15 -9.65,15 -9.65,8.45 -9.807,8.442 -10.114,8.381 -10.404,8.261 -10.665,8.087 -10.887,7.865 -11.061,7.604 -11.181,7.314 -11.242,7.007 -11.25,6.85 -11.242,6.693 -11.181,6.386 -11.061,6.096 -10.887,5.835 -10.665,5.613 -10.404,5.439 -10.114,5.319 -9.807,5.258 -9.65,5.25 -9.65,4.925 -11,4.925 -11,4.55 -11.078,4.546 -11.232,4.516 -11.377,4.456 -11.508,4.368 -11.618,4.258 -11.706,4.127 -11.766,3.982 -11.796,3.828 -11.8,3.75 -11.796,3.672 -11.766,3.518 -11.706,3.373 -11.618,3.242 -11.508,3.132 -11.377,3.044 -11.232,2.984 -11.078,2.954 -11,2.95 -11,-2.95 -11.078,-2.954 -11.232,-2.984 -11.377,-3.044 -11.508,-3.132 -11.618,-3.242 -11.706,-3.373 -11.766,-3.518 -11.796,-3.672 -11.8,-3.75 -11.796,-3.828 -11.766,-3.982 -11.706,-4.127 -11.618,-4.258 -11.508,-4.368 -11.377,-4.456 -11.232,-4.516 -11.078,-4.546 -11,-4.55 -11,-4.9 -9.65,-4.9 -9.65,-5.25 -9.807,-5.258 -10.114,-5.319 -10.404,-5.439 -10.665,-5.613 -10.887,-5.835 -11.061,-6.096 -11.181,-6.386 -11.242,-6.693 -11.25,-6.85 -11.242,-7.007 -11.181,-7.314 -11.061,-7.604 -10.887,-7.865 -10.665,-8.087 -10.404,-8.261 -10.114,-8.381 -9.807,-8.442 -9.65,-8.45 -9.65,-15 -13.25,-15 -13.25,-14.347 -13.247,-14.347 -13.002,-14.335 -12.522,-14.239 -12.07,-14.052 -11.663,-13.78 -11.317,-13.434 -11.045,-13.027 -10.858,-12.575 -10.762,-12.095 -10.75,-11.85 -10.762,-11.605 -10.858,-11.125 -11.045,-10.673 -11.317,-10.266 -11.663,-9.92 -12.07,-9.648 -12.522,-9.461 -13.002,-9.365 -13.247,-9.353 -13.25,-9.353 -13.25,9.353 -13.247,9.353 -13.002,9.365 -12.522,9.461 -12.07,9.648 -11.663,9.92 -11.317,10.266 -11.045,10.673 -10.857,11.125 -10.762,11.605 -10.75,11.85 -10.762,12.095 -10.857,12.575 -11.045,13.027 -11.317,13.434 -11.663,13.78 -12.07,14.052 -12.522,14.239 -13.002,14.335 -13.247,14.347 -13.253,14.347
  region: 13.275,15 9.675,15 9.675,8.45 9.832,8.442 10.139,8.381 10.429,8.261 10.69,8.087 10.912,7.865 11.086,7.604 11.206,7.314 11.267,7.007 11.275,6.85 11.267,6.693 11.206,6.386 11.086,6.096 10.912,5.835 10.69,5.613 10.429,5.439 10.139,5.319 9.832,5.258 9.675,5.25 9.675,4.925 11.025,4.925 11.025,-2.95 11.103,-2.954 11.257,-2.984 11.402,-3.044 11.532,-3.132 11.643,-3.242 11.731,-3.373 11.791,-3.518 11.821,-3.672 11.825,-3.75 11.821,-3.828 11.791,-3.982 11.731,-4.127 11.643,-4.258 11.533,-4.368 11.402,-4.456 11.257,-4.516 11.103,-4.546 11.025,-4.55 11.025,-4.9 9.675,-4.9 9.675,-5.25 9.832,-5.258 10.139,-5.319 10.429,-5.439 10.69,-5.613 10.912,-5.835 11.086,-6.096 11.206,-6.386 11.267,-6.693 11.275,-6.85 11.267,-7.007 11.206,-7.314 11.086,-7.604 10.912,-7.865 10.69,-8.087 10.429,-8.261 10.139,-8.381 9.832,-8.442 9.675,-8.45 9.675,-15 13.275,-15 13.275,-14.347 13.03,-14.335 12.55,-14.24 12.097,-14.053 11.69,-13.781 11.343,-13.435 11.071,-13.028 10.883,-12.575 10.787,-12.095 10.775,-11.85 10.787,-11.605 10.883,-11.125 11.07,-10.673 11.342,-10.266 11.688,-9.92 12.095,-9.648 12.547,-9.461 13.027,-9.365 13.272,-9.353 13.275,9.353 13.03,9.365 12.55,9.46 12.097,9.647 11.69,9.919 11.343,10.265 11.071,10.672 10.883,11.125 10.787,11.605 10.775,11.85 10.787,12.095 10.882,12.575 11.07,13.027 11.342,13.434 11.688,13.78 12.095,14.052 12.547,14.239 13.027,14.335 13.272,14.347
Bottom Layer keep-out:
  region: 194 vertices and 0 holes, not listed, extent -16.275,-14.875 16.263,14.875
  region: 1,-6.247 2.238,-6.25 2.113,-6.1 0.997,-6.198
Top Overlay:
  text "1" at -17.775,10.85 h1.5
Bottom Overlay:
  lines w0.1: 6.542,-1.832 15.371,-9.729 cw(c13.25,-11.85) 11.129,-13.971 2.781,-6.506 ccw(c2.113,-7.25) 2.125,-6.25 1,-6.25 ccw(c0,-6.25) -1,-6.25 -2.125,-6.25 ccw(c-2.113,-7.25) -2.781,-6.506 -11.129,-13.971 cw(c-13.25,-11.85) -15.371,-9.729 -6.625,-1.906 ccw(c-7.25,-1.125) -6.25,-1.125 -6.25,1.125 ccw(c-7.25,1.125) -6.625,1.906 -15.371,9.729 cw(c-13.25,11.85) -11.129,13.971 -2.781,6.506 ccw(c-2.113,7.25) -2.125,6.25 2.125,6.25 ccw(c2.113,7.25) 2.781,6.506 11.129,13.971 cw(c13.25,11.85) 15.371,9.729 6.625,1.906 ccw(c7.25,1.125) 6.25,1.125 6.25,-1.125 ccw(c7.25,-1.125) 6.625,-1.906
Top Solder:
  rectangle: -17.25,-15 17.25,15
M14-Top Assembly:
  drawing of 1377 lines, arcs and shapes, not listed
  text "N13" at 2.4,-4.129 h0.8
  text "N1" at -3.375,-4.104 h0.8
  text "A13" at 2.375,3.621 h0.8
  text "A1" at -3.375,3.621 h0.8
  text "'.Designator'" at -2,3.5 h0.75
M15-Bottom Assembly:
  circle w0.01: c13.25,11.85 r2.5
  circle w0.01: c13.25,11.85 r1.075
  circle w0.01: c13.25,-11.85 r2.5
  circle w0.01: c13.25,-11.85 r1.075
  circle w0.01: c-13.25,-11.85 r2.5
  circle w0.01: c-13.25,-11.85 r1.075
  circle w0.01: c-13.25,11.85 r2.5
  circle w0.01: c-13.25,11.85 r1.075
  lines w0.01: 6.542,-1.832 15.371,-9.729 cw(c13.25,-11.85) 11.129,-13.971 2.781,-6.506 ccw(c2.113,-7.25) 2.125,-6.25 1,-6.25 ccw(c0,-6.25) -1,-6.25 -2.125,-6.25 ccw(c-2.113,-7.25) -2.781,-6.506 -11.129,-13.971 cw(c-13.25,-11.85) -15.371,-9.729 -6.625,-1.906 ccw(c-7.25,-1.125) -6.25,-1.125 -6.25,1.125 ccw(c-7.25,1.125) -6.625,1.906 -15.371,9.729 cw(c-13.25,11.85) -11.129,13.971 -2.781,6.506 ccw(c-2.113,7.25) -2.125,6.25 2.125,6.25 ccw(c2.113,7.25) 2.781,6.506 11.129,13.971 cw(c13.25,11.85) 15.371,9.729 6.625,1.906 ccw(c7.25,1.125) 6.25,1.125 6.25,-1.125 ccw(c7.25,-1.125) 6.625,-1.906
M16-Top Courtyard:
  lines w0.01: -10.3,-2.4 -10.3,2.4 ; -5.33,-9.1 -5.33,-5.51 5.33,-5.51 5.33,-9.1 ; -5.33,9.1 -5.33,5.51 5.33,5.51 5.33,9.1 ; 10.3,-2.4 10.3,2.4 ; -9.55,11.8 -7.55,11.8 -7.55,9.1 7.55,9.1 7.55,11.8 9.55,11.8 9.55,15 -9.55,15 ; -9.55,11.8 -9.55,15 ; -9.55,11.8 -9.55,15 ; 17.25,15 -17.25,15 -17.25,-15 32.25,-15 ; 17.25,15 17.25,-15 32.25,-15 ; 17.25,15 32.25,15 32.25,-15 ; -17.25,-7.8 -17.25,7.8 -12.35,7.8 -12.35,2.4 -7.39,2.4 -7.39,-2.4 -13.95,-2.4 -13.95,-7.8 -17.25,-7.8 ; -9.55,-15 -9.55,-11.8 -7.55,-11.8 -7.55,-9.1 7.55,-9.1 7.55,-11.8 9.55,-11.8 9.55,-15 -9.55,-15 ; 7.39,-2.4 12.35,-2.4 12.35,-7.8 17.25,-7.8 17.25,7.8 12.35,7.8 12.35,2.4 7.39,2.4 7.39,-2.4
  text "ZONE." at -10.111,0.938 h0.7
  text "RESTRICTION" at -9.424,2.063 h0.7
  text "COMP HEIGHT" at -8.812,2.312 h0.7
  text "2.0MM MAX" at -8.083,1.75 h0.7
  text "HEIGHT RESTRICTION ZONE." at -16.424,6.39 h1
  text "2.5MM MAXIMUM COMPONENT" at -15.154,6.75 h1
  text "2.5MM MAXIMUM COMPONENT" at -6.75,-11.529 h1
  text "HEIGHT RESTRICTION ZONE." at -6.39,-12.799 h1
  text "2.0MM MAXIMUM" at -3.75,-6.646 h1
  text "COMPONENT HEIGHT" at -4.75,-7.654 h1
  text "RESTRICTION ZONE." at -4.64,-8.674 h1
  text "RESTRICTION ZONE." at 4.64,8.674 h1
  text "COMPONENT HEIGHT" at 4.75,7.654 h1
  text "2.0MM MAXIMUM" at 3.75,6.646 h1
  text "HEIGHT RESTRICTION ZONE." at 6.39,12.799 h1
  text "2.5MM MAXIMUM COMPONENT" at 6.75,11.529 h1
  text "2.5MM MAXIMUM COMPONENT" at 14.444,-6.75 h1
  text "HEIGHT RESTRICTION ZONE." at 15.714,-6.39 h1
  text "2.0MM MAX" at 8.083,-1.75 h0.7
  text "COMP HEIGHT" at 8.812,-2.312 h0.7
  text "RESTRICTION" at 9.424,-2.063 h0.7
  text "ZONE." at 10.112,-0.938 h0.7
  text "(MAX HEIGHT 3.5MM)" at 27.08,-9.25 h2
  text "COVER KEEP OUT AREA" at 23.714,-10.75 h2
M17-Bottom Courtyard:
  lines w0.01: 6.542,-1.832 15.371,-9.729 cw(c13.25,-11.85) 11.129,-13.971 2.781,-6.506 ccw(c2.113,-7.25) 2.125,-6.25 1,-6.25 ccw(c0,-6.25) -1,-6.25 -2.125,-6.25 ccw(c-2.113,-7.25) -2.781,-6.506 -11.129,-13.971 cw(c-13.25,-11.85) -15.371,-9.729 -6.625,-1.906 ccw(c-7.25,-1.125) -6.25,-1.125 -6.25,1.125 ccw(c-7.25,1.125) -6.625,1.906 -15.371,9.729 cw(c-13.25,11.85) -11.129,13.971 -2.781,6.506 ccw(c-2.113,7.25) -2.125,6.25 2.125,6.25 ccw(c2.113,7.25) 2.781,6.506 11.129,13.971 cw(c13.25,11.85) 15.371,9.729 6.625,1.906 ccw(c7.25,1.125) 6.25,1.125 6.25,-1.125 ccw(c7.25,-1.125) 6.625,-1.906
3D body: height -1.6, standoff -3.6, extent -16.25,-14.875 16.262,14.875
3D body: height 4, standoff 3, extent -13,-14.35 -10.75,-12.1
3D body: height 4, standoff 3, extent -15.75,-14.35 -13.5,-12.1
3D body: height 4, standoff 3, extent -13,-11.6 -10.75,-9.35
3D body: height 4, standoff 3, extent -15.75,-11.6 -13.5,-9.35
3D body: height 3, standoff 2, extent -15.75,-14.347 -10.75,-9.353
3D body: height 4.4, standoff -3.6, extent -14.316,-12.923 -12.175,-10.777
3D body: height 4, standoff 3, extent -13,9.35 -10.75,11.6
3D body: height 4, standoff 3, extent -15.75,9.35 -13.5,11.6
3D body: height 4, standoff 3, extent -13,12.1 -10.75,14.35
3D body: height 4, standoff 3, extent -15.75,12.1 -13.5,14.35
3D body: height 3, standoff 2, extent -15.75,9.353 -10.75,14.347
3D body: height 4.4, standoff -3.6, extent -14.316,10.777 -12.175,12.923
3D body: height 4, standoff 3, extent 13.5,9.35 15.75,11.6
3D body: height 4, standoff 3, extent 10.75,9.35 13,11.6
3D body: height 4, standoff 3, extent 13.5,12.1 15.75,14.35
3D body: height 4, standoff 3, extent 10.75,12.1 13,14.35
3D body: height 3, standoff 2, extent 10.75,9.353 15.75,14.347
3D body: height 4.4, standoff -3.6, extent 12.184,10.777 14.325,12.923
3D body: height 4, standoff 3, extent 13.5,-14.35 15.75,-12.1
3D body: height 4, standoff 3, extent 10.75,-14.35 13,-12.1
3D body: height 4, standoff 3, extent 13.5,-11.6 15.75,-9.35
3D body: height 4, standoff 3, extent 10.75,-11.6 13,-9.35
3D body: height 3, standoff 2, extent 10.75,-14.347 15.75,-9.353
3D body: height 4.4, standoff -3.6, extent 12.184,-12.923 14.325,-10.777
3D body: height 22, standoff 0, extent -16.75,-14.5 16.75,14.5
3D body "5C-042-342-01_IC_SOCKET_Close.STEP": height 21.5, standoff -1.4, extent -16.75,-14.5 16.75,14.5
